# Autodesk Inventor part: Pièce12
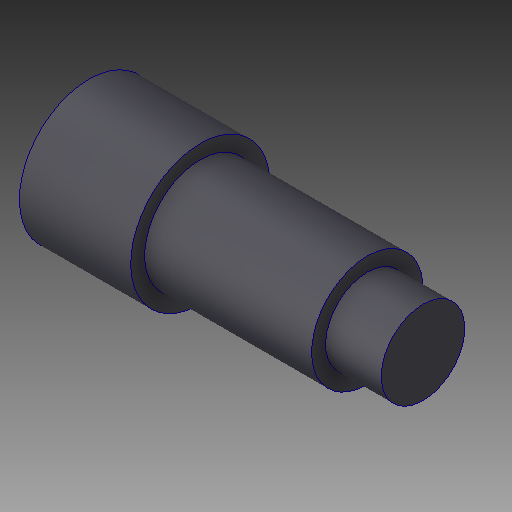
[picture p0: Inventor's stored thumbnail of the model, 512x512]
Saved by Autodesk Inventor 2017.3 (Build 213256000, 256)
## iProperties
Created: 2007-11
Part Number: Pièce12
Material: Générique
Document SubType Name: Modeling
Designer: ficho
Density: 1 g/cm^3
Appearance: Par défaut
Author: ficho
Sending System: SolidWorks 2009
Last Author: christophe
Last Saved: 2011-02-10
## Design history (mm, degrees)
feature "Révolution1"
node "Solide1"
